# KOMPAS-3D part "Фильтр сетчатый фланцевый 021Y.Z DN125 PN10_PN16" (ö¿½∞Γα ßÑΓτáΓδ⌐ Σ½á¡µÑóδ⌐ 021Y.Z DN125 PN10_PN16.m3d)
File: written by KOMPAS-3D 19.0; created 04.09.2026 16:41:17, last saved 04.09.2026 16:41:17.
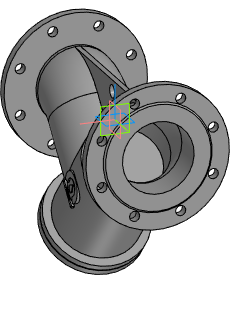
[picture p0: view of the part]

Document properties: Автор: Энергия; Полное имя файла: Z:\3.Личные\sachek\Dendor\_3D для проектировщиков\8.1 Фильтр сетчатый 021Y.Z\021Y.Z_STP\Фильтр сетчатый фланцевый 021Y.Z DN125 PN10_PN16.m3d

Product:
- Part/product: Фильтр сетчатый фланцевый 021Y.Z DN125 PN10_PN16

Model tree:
1. Операция без истории:1  (labels: Фильтр сетчатый фланцевый 021Y.Z DN125 PN10_PN16)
